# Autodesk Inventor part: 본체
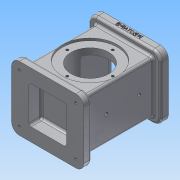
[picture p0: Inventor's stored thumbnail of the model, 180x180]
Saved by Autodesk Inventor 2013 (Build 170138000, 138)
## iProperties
Created: 2017-08
Part Number: 본체
Material: 알루미늄 6061
Document SubType Name: Modeling
Designer: Administrator
Density: 2.71 g/cm^3
Mass: 871.233 g
Surface Area: 645.609 cm^2
Volume: 321.488 cm^3
Author: Administrator
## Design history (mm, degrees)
sketch "스케치1"
  geometry: L1 (-37, -44)-(37, -44); L2 (37, -44)-(37, 44); L3 (37, 44)-(-37, 44); L4 (-37, 44)-(-37, -44); L5 (-37, -44)-(37, 44); L6 (37, -44)-(-37, 44); 1 further point
  constraints: 12 end point, 2 midpoint, 2 parallel, 1 horizontal, 1 perpendicular
  dimensions: "d2" = 74 distance of L3.end L2.end; "d3" = 88 distance of L1.end L2.end
extrude "돌출1" new body sketch "스케치1" distance "d4" = 33; taper "d5" = 0 deg
sketch "스케치2"
  geometry: L1 (-37, -44)-(37, -44) reference; 2 further points
  constraints: 1 coincident
  dimensions: "d8" = 44 distance from line of L1 point (0, 0)
hole "구멍1" sketch "스케치2" at (0, 0) diameter "d9" = 48; stored, may be unused: countersink angle "d13" = 90 deg, drill point angle "d15" = 118 deg; dims "d10" = 6, "d11" = 70, "d12" = 3, "d14" = 8
sketch "스케치3"
  geometry: C1 r 35 at (0, 0) reference; 1 further point
  constraints: 1 vertical alignment
  dimensions: "d16" = 29 distance of C1.centre point (0, 29)
hole "구멍2" sketch "스케치3" at (0, 29) diameter "d17" = 3.242; stored, may be unused: countersink angle "d21" = 90 deg, drill point angle "d23" = 118 deg; dims "d18" = 4, "d19" = 70, "d20" = 6, "d22" = 6
sketch "스케치5"
  geometry: L1 (-9, -8)-(83, -8); L2 (83, -8)-(83, 74); L3 (83, 74)-(-9, 74); L4 (-9, 74)-(-9, -8); L5 (-9, -8)-(83, 74); L6 (83, -8)-(-9, 74); 1 further point
  constraints: 12 end point, 2 midpoint, 2 parallel, 1 horizontal, 1 perpendicular
  dimensions: "d29" = 92 distance of L2.end L3.end; "d31" = 82 distance of L1.end L2.end
extrude "돌출2" join sketch "스케치5" distance "d32" = 10; taper "d33" = 0 deg
sketch "스케치6"
  geometry: 5 further points
  constraints: 2 horizontal alignment, 2 vertical alignment
  dimensions: "d34" = 72 distance of point (1, 64) point (73, 64); "d36" = 62 distance of point (73, 2) point (73, 64); "d37" = 36 horizontal distance of point (37, 33) point (1, 64); "d38" = 31 vertical distance of point (73, 2) point (37, 33)
hole "구멍3" sketch "스케치6" at (1, 64), (73, 64), (1, 2), (73, 2) diameter "d39" = 3.242; stored, may be unused: countersink angle "d43" = 90 deg, drill point angle "d45" = 118 deg; dims "d40" = 4, "d41" = 70, "d42" = 6, "d44" = 6
fillet "모깎기1" dims "d46" = 10
sketch "스케치7"
  geometry: L1 (2, -98)-(64, -98) reference; 3 further points
  constraints: 2 vertical alignment
  dimensions: "d47" = 38 distance from line of point (33, -60) L1; "d48" = 42 distance of point (33, -18) point (33, -60)
hole "구멍4" sketch "스케치7" at (33, -60), (33, -18) diameter "d49" = 4.134; stored, may be unused: countersink angle "d53" = 90 deg, drill point angle "d55" = 118 deg; dims "d50" = 4, "d51" = 70, "d52" = 6, "d54" = 30
sketch "스케치8"
  geometry: L1 (11, 7)-(63, 7); L2 (63, 7)-(63, 59); L3 (63, 59)-(11, 59); L4 (11, 59)-(11, 7); L5 (11, 7)-(63, 59); L6 (63, 7)-(11, 59); 2 further points
  constraints: 12 end point, 2 midpoint, 2 parallel, 1 coincident, 1 horizontal, 1 perpendicular
  dimensions: "d56" = 52 distance of L3.end L2.end; "d58" = 52 distance of L1.end L2.end
extrude "돌출3" cut sketch "스케치8" distance "d59" = 8; taper "d60" = 0 deg
sketch "스케치9"
  geometry: L1 (15, 11)-(59, 11); L2 (59, 11)-(59, 55); L3 (59, 55)-(15, 55); L4 (15, 55)-(15, 11); L5 (15, 11)-(59, 55); L6 (59, 11)-(15, 55); 1 further point
  constraints: 12 end point, 2 midpoint, 2 parallel, 1 horizontal, 1 perpendicular
  dimensions: "d61" = 44 distance of L3.end L2.end; "d62" = 44 distance of L2.end L1.end
extrude "돌출4" cut sketch "스케치9" distance "d63" = 74; taper "d64" = 0 deg
sketch "스케치10"
  geometry: L1 (12, -65)-(60, -65); L2 (60, -65)-(60, -17); L3 (60, -17)-(12, -17); L4 (12, -17)-(12, -65); L5 (12, -65)-(60, -17); L6 (60, -65)-(12, -17); 1 further point
  constraints: 12 end point, 2 midpoint, 2 parallel, 1 horizontal, 1 perpendicular
  dimensions: "d65" = 48 distance of L3.end L2.end; "d66" = 48 distance of L2.end L1.end
extrude "돌출5" cut sketch "스케치10" distance "d67" = 16; taper "d68" = 0 deg
fillet "모깎기2" dims "d69" = 3
chamfer "모따기1" distance "d70" = 1; stored, may be unused: second distance "d71" = 2, angle "d72" = 45 deg
sketch "스케치11"
  geometry: L1 (0, 0)-(72, 0) reference; L2 (-10, 0)-(-10, -7) reference; 2 further points
  constraints: 1 other
  dimensions: "d73" = 46 distance from line of L2 point (36, -4); "d74" = 4 distance from line of L1 point (36, -4)
feature "엠보싱1" sketch "스케치11" dims "d75" = 0.5, "d76" = 0
node "솔리드1"
pattern_circular "원형 패턴1" dims angle "d25" = 360 deg
mirror "대칭1"
mirror "대칭2"
